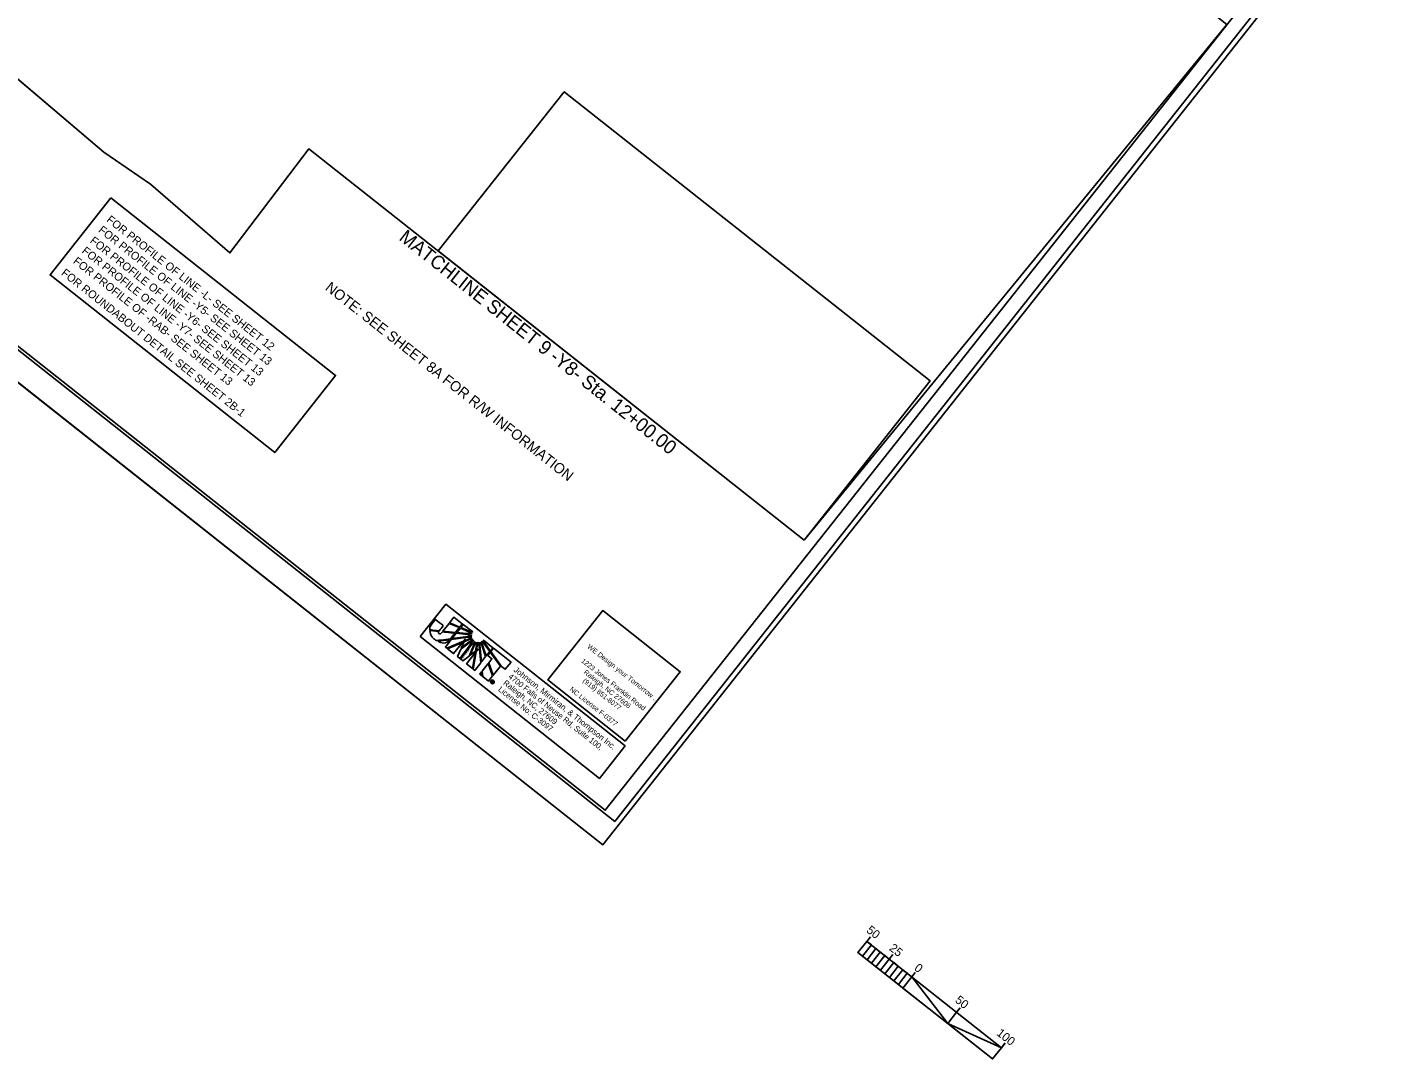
# Model space of a CAD drawing. Extents: x 557005 to 559009, y 505746 to 507841.
# Drawn here: x 557823 to 559009, y 505746 to 506649 of the extents above; entities that cross this region are included whole.
import ezdxf

# ---------------------------------------------------------------- set-up
doc = ezdxf.new("R2010")
doc.units = 0
for name, color, linetype in [('Matchline', 7, 'Continuous'), ('Matchline Text', 7, 'Continuous'), ('Prop DSN Text', 7, 'Continuous'), ('Prop Horizontal Alignment Curve and Spiral Data', 7, 'Continuous'), ('Scratch_Level_5', 7, 'Continuous'), ('Sheet Border Standard 30in CELL', 7, 'Continuous'), ('Sheet Cutting Line CELL', 7, 'Continuous'), ('Sheet Data Field CELL', 7, 'Continuous'), ('Sheet Plot Border Inside CELL', 7, 'Continuous'), ('Sheet Plot Border Outside CELL', 7, 'Continuous'), ('Sheet Title CELL', 7, 'Continuous')]:
    doc.layers.add(name, color=color, linetype=linetype)

msp = doc.modelspace()

# ---------------------------------------------------------------- linework, layer by layer
at = {"layer": 'Matchline'}
for p, q in [((557889.7, 506539.4), (557425.5, 506933.6)), ((558069.2, 506542.3), (558000.1, 506451.2)), ((558069.1, 506542.3), (558502.2, 506199.9)), ((558285.6, 506371.1), (558289.5, 506368)), ((558191.7, 506127), (558186.3, 506120.2)), ((558200.7, 506123.3), (558191.7, 506127)), ((558196, 506132.5), (558192.1, 506127.6)), ((558192.1, 506127.6), (558201.1, 506123.8)), ((558203.3, 506126.7), (558196, 506132.5)), ((558197.3, 506119), (558200.7, 506123.3)), ((558201.1, 506123.8), (558203.3, 506126.7)), ((558204.1, 506126.1), (558202.1, 506123.5)), ((558202.1, 506123.5), (558209.6, 506120.3)), ((558212.4, 506119.6), (558204.1, 506126.1)), ((558186.3, 506120.2), (558197.3, 506119)), ((558193.7, 506112.9), (558188.5, 506106.3)), ((558189.7, 506105.3), (558204.3, 506111.4)), ((558208.5, 506115), (558193.7, 506112.9)), ((558198, 506118.3), (558194.3, 506113.7)), ((558194.3, 506113.7), (558208.5, 506115.6)), ((558207.5, 506117.3), (558198, 506118.3)), ((558201.6, 506122.9), (558198.5, 506118.9)), ((558198.5, 506118.9), (558206.7, 506118.1)), ((558209.1, 506119.7), (558201.6, 506122.9)), ((558204.3, 506111.4), (558205.8, 506113.3)), ((558209.2, 506112.8), (558204.8, 506110.9)), ((558205.8, 506113.3), (558205.1, 506111.7)), ((558205.1, 506111.7), (558208.8, 506113.3)), ((558206.7, 506118.1), (558211.7, 506118.1)), ((558211.4, 506116.5), (558207.5, 506117.3)), ((558208.5, 506115.6), (558211.4, 506116.5)), ((558211.6, 506115), (558208.5, 506115)), ((558208.8, 506113.3), (558211.6, 506115)), ((558208.8, 506106.1), (558213.1, 506112.2)), ((558211.7, 506118.1), (558209.1, 506119.7)), ((558212.1, 506113.5), (558209.2, 506112.8)), ((558209.6, 506120.3), (558212.4, 506119.6)), ((558210.1, 506111.4), (558212.1, 506113.5)), ((558213.1, 506112.2), (558210.2, 506110.6)), ((558229.9, 506105.7), (558221.8, 506112.2)), ((558221.8, 506112.2), (558223.1, 506109.6)), ((558188.5, 506106.3), (558189.7, 506105.3)), ((558203.4, 506110.4), (558190.3, 506104.8)), ((558190.3, 506104.8), (558195.7, 506100.5)), ((558195.7, 506100.5), (558203.4, 506110.4)), ((558201.9, 506104.3), (558199.1, 506097.9)), ((558201.1, 506096.3), (558208.8, 506106.1)), ((558209.4, 506105.7), (558201.6, 506095.9)), ((558210.2, 506110.6), (558201.9, 506104.3)), ((558202.4, 506105.5), (558210.1, 506111.4)), ((558204.8, 506110.9), (558202.4, 506105.5)), ((558214.6, 506101.2), (558207.1, 506091.6)), ((558209.2, 506098.4), (558213.4, 506108.1)), ((558214.3, 506111.2), (558209.4, 506105.7)), ((558214.1, 506108.1), (558210.2, 506099.2)), ((558210.2, 506099.2), (558214.9, 506102.7)), ((558212.3, 506087.5), (558214.6, 506101.2)), ((558215.4, 506102.2), (558212.9, 506087)), ((558213.4, 506108.1), (558214.3, 506111.2)), ((558215.7, 506110.6), (558214.1, 506108.1)), ((558214.9, 506102.7), (558215.7, 506107.6)), ((558217.1, 506104.4), (558215.4, 506102.2)), ((558216.3, 506107.4), (558215.6, 506103.2)), ((558215.6, 506103.2), (558217.1, 506104.4)), ((558215.7, 506107.6), (558215.7, 506110.6)), ((558217.3, 506110.5), (558216.3, 506107.4)), ((558218.1, 506107.4), (558217.3, 506110.5)), ((558219.4, 506092.5), (558218.1, 506107.4)), ((558218.9, 506110.7), (558218.7, 506107.5)), ((558218.7, 506107.5), (558220, 506093.3)), ((558220.6, 506107), (558218.9, 506110.7)), ((558220.4, 506111.3), (558221.5, 506106.3)), ((558222.4, 506109.2), (558220.4, 506111.3)), ((558223.7, 506098), (558220.6, 506107)), ((558221.5, 506106.3), (558224.2, 506098.7)), ((558227.4, 506102.5), (558222.4, 506109.2)), ((558223.1, 506109.6), (558227.8, 506103.1)), ((558224.2, 506098.7), (558227.4, 506102.5)), ((558227.8, 506101.9), (558225.5, 506098.9)), ((558227.8, 506103.1), (558229.9, 506105.7)), ((558227.8, 506101.9), (558227.8, 506101.9)), ((558236.7, 506089.7), (558227.8, 506101.9)), ((558230.5, 506105.3), (558228.2, 506102.5)), ((558228.2, 506102.5), (558228.2, 506102.4)), ((558228.2, 506102.4), (558237.7, 506089.4)), ((558245.9, 506093.1), (558230.5, 506105.3)), ((558199.1, 506097.9), (558201.1, 506096.3)), ((558201.6, 506095.9), (558203.7, 506094.3)), ((558203.7, 506094.3), (558209.2, 506098.4)), ((558207.1, 506091.6), (558212.3, 506087.5)), ((558214.2, 506085.9), (558219.4, 506092.5)), ((558220, 506093.3), (558223.7, 506098)), ((558226, 506091.8), (558220.8, 506085.3)), ((558225.5, 506098.9), (558229.2, 506096)), ((558229.8, 506081), (558226, 506091.8)), ((558229.2, 506096), (558226.4, 506092.4)), ((558226.4, 506092.4), (558230.3, 506081.6)), ((558230.3, 506081.6), (558236.7, 506089.7)), ((558237.7, 506089.4), (558240.9, 506086.8)), ((558240.9, 506086.8), (558245.9, 506093.1)), ((558212.9, 506087), (558214.2, 506085.9)), ((558220.2, 506084.5), (558218.6, 506082.5)), ((558218.6, 506082.5), (558220.5, 506081)), ((558220.5, 506081), (558220.2, 506084.5)), ((558220.8, 506085.3), (558221.2, 506080.4)), ((558221.2, 506080.4), (558226.2, 506076.5)), ((558226.2, 506076.5), (558229.8, 506081)), ((558228.7, 506075.6), (558229.6, 506076.8)), ((558229.3, 506075.9), (558228.9, 506075.4)), ((558229.5, 506075.7), (558229.3, 506075.9)), ((558229.7, 506076.3), (558229.5, 506076.1)), ((558229.5, 506076.1), (558229.7, 506075.9)), ((558229.7, 506075.9), (558229.5, 506075.7)), ((558229.5, 506075.7), (558229.7, 506075.9)), ((558229.6, 506076.8), (558230, 506076.4)), ((558229.9, 506076.2), (558229.7, 506076.3)), ((558229.7, 506075.9), (558229.7, 506075.9)), ((558230, 506076.4), (558229.9, 506076.2)), ((558229.9, 506076.2), (558230, 506076.4)), ((558229.9, 506076.2), (558229.9, 506076.2)), ((558230, 506076.4), (558230.1, 506076.3)), ((558230.6, 506077.1), (558230.4, 506076.8)), ((558230.4, 506076.8), (558230.6, 506077.1)), ((558228.8, 506074.8), (558228.6, 506074.6)), ((558228.6, 506074.6), (558228.8, 506074.8)), ((558228.6, 506074.6), (558228.6, 506074.6)), ((558228.9, 506075.4), (558228.7, 506075.6)), ((558228.8, 506074.8), (558228.8, 506074.8)), ((558229.5, 506075.7), (558229.5, 506075.7))]:
    msp.add_line(p, q, dxfattribs=at)
msp.add_lwpolyline([(558166.4, 506115.5), (558323.3, 505991.4), (558345.7, 506019.7), (558188.8, 506143.8)], close=True, dxfattribs=at)
for points in [[(558186.3, 506120.2), (558197.3, 506119), (558200.7, 506123.3), (558191.7, 506127), (558186.3, 506120.2)], [(558192.1, 506127.6), (558201.1, 506123.8), (558203.3, 506126.7), (558196, 506132.5), (558192.1, 506127.6)], [(558209.6, 506120.3), (558212.4, 506119.6), (558204.1, 506126.1), (558202.1, 506123.5), (558209.6, 506120.3)], [(558211.6, 506115), (558208.5, 506115), (558193.7, 506112.9), (558188.5, 506106.3), (558189.7, 506105.3), (558204.3, 506111.4), (558205.8, 506113.3), (558205.1, 506111.7), (558208.8, 506113.3), (558211.6, 506115)], [(558198, 506118.3), (558194.3, 506113.7), (558208.5, 506115.6), (558211.4, 506116.5), (558207.5, 506117.3), (558198, 506118.3)], [(558201.6, 506122.9), (558198.5, 506118.9), (558206.7, 506118.1), (558211.7, 506118.1), (558209.1, 506119.7), (558201.6, 506122.9)], [(558210.2, 506110.6), (558201.9, 506104.3), (558199.1, 506097.9), (558201.1, 506096.3), (558208.8, 506106.1), (558213.1, 506112.2), (558210.2, 506110.6)], [(558212.1, 506113.5), (558209.2, 506112.8), (558204.8, 506110.9), (558202.4, 506105.5), (558210.1, 506111.4), (558212.1, 506113.5)], [(558223.1, 506109.6), (558227.8, 506103.1), (558229.9, 506105.7), (558221.8, 506112.2), (558223.1, 506109.6)], [(558190.3, 506104.8), (558195.7, 506100.5), (558203.4, 506110.4), (558190.3, 506104.8)], [(558214.3, 506111.2), (558209.4, 506105.7), (558201.6, 506095.9), (558203.7, 506094.3), (558209.2, 506098.4), (558213.4, 506108.1), (558214.3, 506111.2)], [(558207.1, 506091.6), (558212.3, 506087.5), (558214.6, 506101.2), (558207.1, 506091.6)], [(558215.7, 506110.6), (558214.1, 506108.1), (558210.2, 506099.2), (558214.9, 506102.7), (558215.7, 506107.6), (558215.7, 506110.6)], [(558217.3, 506110.5), (558216.3, 506107.4), (558215.6, 506103.2), (558217.1, 506104.4), (558215.4, 506102.2), (558212.9, 506087), (558214.2, 506085.9), (558219.4, 506092.5), (558218.1, 506107.4), (558217.3, 506110.5)], [(558218.9, 506110.7), (558218.7, 506107.5), (558220, 506093.3), (558223.7, 506098), (558220.6, 506107), (558218.9, 506110.7)], [(558220.4, 506111.3), (558221.5, 506106.3), (558224.2, 506098.7), (558227.4, 506102.5), (558222.4, 506109.2), (558220.4, 506111.3)], [(558227.8, 506101.9), (558227.8, 506101.9), (558225.5, 506098.9), (558229.2, 506096), (558226.4, 506092.4), (558230.3, 506081.6), (558236.7, 506089.7), (558227.8, 506101.9)], [(558245.9, 506093.1), (558230.5, 506105.3), (558228.2, 506102.5), (558228.2, 506102.4), (558237.7, 506089.4), (558240.9, 506086.8), (558245.9, 506093.1)], [(558226, 506091.8), (558220.8, 506085.3), (558221.2, 506080.4), (558226.2, 506076.5), (558229.8, 506081), (558226, 506091.8), (558226, 506091.8)], [(558218.6, 506082.5), (558218.6, 506082.5), (558220.5, 506081), (558220.2, 506084.5), (558218.6, 506082.5)], [(558229.8, 506075.2), (558229.8, 506075.1), (558229.8, 506075), (558229.7, 506075), (558229.7, 506074.9), (558229.4, 506075)]]:
    msp.add_lwpolyline(points, dxfattribs=at)
for points, degree in [([(558186.7, 506125), (558186.7, 506125), (558179.9, 506130.4), (558179.9, 506130.4), (558179.9, 506130.4), (558176.5, 506126.1), (558176.5, 506126.1), (558176.5, 506126.1), (558176.2, 506125.7), (558176.2, 506125.7), (558175.1, 506124.3), (558174.7, 506122.9), (558174.8, 506121.4), (558174.8, 506121.4), (558183.1, 506120.4), (558183.1, 506120.5), (558183.1, 506120.5), (558186.7, 506125), (558186.7, 506125)], 3), ([(558182.9, 506118), (558182.5, 506118.4), (558182.3, 506118.9), (558182.8, 506119.9), (558182.8, 506119.9), (558174.9, 506120.8), (558174.9, 506120.8), (558175.2, 506117.8), (558177, 506114.7), (558179.2, 506113), (558179.7, 506112.5), (558180.2, 506112.2), (558180.9, 506111.9), (558180.9, 506111.9), (558192.9, 506113.5), (558192.9, 506113.5), (558192.9, 506113.5), (558196.8, 506118.4), (558196.8, 506118.4), (558196.8, 506118.4), (558185.8, 506119.6), (558185.8, 506119.6), (558184.3, 506117.7), (558183.5, 506117.6), (558182.9, 506118)], 3), ([(558182.9, 506118), (558182.5, 506118.4), (558182.3, 506118.9), (558182.8, 506119.9), (558182.8, 506119.9), (558174.9, 506120.8), (558174.9, 506120.8), (558175.2, 506117.8), (558177, 506114.7), (558179.2, 506113), (558179.7, 506112.5), (558180.2, 506112.2), (558180.9, 506111.9), (558180.9, 506111.9), (558192.9, 506113.5), (558192.9, 506113.5), (558192.9, 506113.5), (558196.8, 506118.4), (558196.8, 506118.4), (558196.8, 506118.4), (558185.8, 506119.6), (558185.8, 506119.6), (558184.3, 506117.7), (558183.5, 506117.6), (558182.9, 506118)], 3), ([(558192.3, 506112.7), (558192.3, 506112.7), (558181.9, 506111.3), (558181.9, 506111.3), (558185.3, 506109.8), (558189.5, 506109.5), (558192.3, 506112.7)], 3), ([(558228.6, 506074.6), (558228.3, 506074.9), (558228.1, 506075.2), (558228, 506075.7), (558228, 506076.1), (558228.1, 506076.5), (558228.3, 506076.8), (558228.6, 506077.2), (558229, 506077.4), (558229.4, 506077.4), (558229.8, 506077.4), (558230.2, 506077.3), (558230.6, 506077.1)], 3), ([(558230.4, 506076.8), (558230.1, 506077), (558229.8, 506077.1), (558229.5, 506077.1), (558229.1, 506077.1), (558228.8, 506076.9), (558228.6, 506076.6), (558228.4, 506076.3), (558228.3, 506076), (558228.3, 506075.7), (558228.4, 506075.3), (558228.5, 506075.1), (558228.8, 506074.8)], 3), ([(558228.8, 506074.8), (558229.1, 506074.6), (558229.4, 506074.5), (558229.7, 506074.6), (558230.1, 506074.6), (558230.4, 506074.8), (558230.6, 506075), (558230.8, 506075.3), (558230.9, 506075.6), (558230.9, 506076), (558230.8, 506076.3), (558230.7, 506076.6), (558230.4, 506076.8)], 3), ([(558229.7, 506075.9), (558229.8, 506075.8), (558230, 506075.8), (558230, 506075.9), (558230.1, 506075.9), (558230.1, 506076), (558229.9, 506076.2)], 3), ([(558230.1, 506076.3), (558230.4, 506076.1), (558230.4, 506075.9), (558230.3, 506075.7), (558230.2, 506075.6), (558230.1, 506075.5), (558229.9, 506075.5)], 3), ([(558230.6, 506077.1), (558230.9, 506076.8), (558231.1, 506076.4), (558231.2, 506076), (558231.2, 506075.6), (558231.1, 506075.2), (558230.8, 506074.8)], 3), ([(558230.8, 506074.8), (558230.6, 506074.5), (558230.2, 506074.3), (558229.8, 506074.2), (558229.4, 506074.2), (558229, 506074.3), (558228.6, 506074.6)], 3), ([(558229.4, 506075), (558229.5, 506075.1), (558229.5, 506075.2), (558229.6, 506075.3), (558229.6, 506075.4), (558229.7, 506075.5), (558229.7, 506075.5)], 3), ([(558229.7, 506075.5), (558229.7, 506075.6), (558229.6, 506075.6), (558229.5, 506075.7)], 2), ([(558229.9, 506075.5), (558230, 506075.4), (558230, 506075.3), (558229.8, 506075.2)], 2)]:
    msp.add_open_spline(points, degree=degree, dxfattribs=at)
at = {"layer": 'Prop DSN Text'}
msp.add_lwpolyline([(558345.9, 506024), (558278.2, 506077.5), (558326.1, 506138.2), (558393.9, 506084.7)], close=True, dxfattribs=at)
at = {"layer": 'Prop Horizontal Alignment Curve and Spiral Data'}
msp.add_lwpolyline([(557895.9, 506499.3), (557842.7, 506432), (558039.2, 506276.6), (558092.5, 506344), (557895.9, 506499.3)], dxfattribs=at)
at = {"layer": 'Scratch_Level_5'}
for points in [[(558502.2, 506199.9), (558069.1, 506542.3), (558000.1, 506451.2), (557930.7, 506511.3), (557889.7, 506539.4), (557425.5, 506933.6), (557393.3, 506960), (557371.4, 506969.7), (557385.3, 506999.1), (557443.2, 507138.3), (557378.9, 507175.5), (557803.8, 507716.9), (558807.2, 506891.6), (558715.1, 506775.1), (558872, 506651)], [(558502.2, 506199.9), (558182.2, 506452.9), (558292.5, 506592.3), (558612.5, 506339.3)]]:
    msp.add_lwpolyline(points, close=True, dxfattribs=at)
at = {"layer": 'Sheet Border Standard 30in CELL'}
msp.add_lwpolyline([(558979.7, 506787.1), (557803.1, 507717.5), (557151.8, 506893.8), (558328.4, 505963.5)], close=True, dxfattribs=at)
at = {"layer": 'Sheet Cutting Line CELL'}
msp.add_line((557005.3, 506977.8), (558326.3, 505933.3), dxfattribs=at)
at = {"layer": 'Sheet Data Field CELL'}
for p, q in [((558557.2, 505848.7), (558560.3, 505852.6)), ((558576.8, 505833.2), (558579.9, 505837.1)), ((558635.6, 505786.7), (558638.7, 505790.6)), ((558674.9, 505755.7), (558678, 505759.6))]:
    msp.add_line(p, q, dxfattribs=at)
at = {"layer": 'Sheet Plot Border Inside CELL'}
msp.add_lwpolyline([(558991.1, 506781.4), (557683.8, 507815), (557029.4, 506987.4), (558336.7, 505953.7)], close=True, dxfattribs=at)
at = {"layer": 'Sheet Plot Border Outside CELL'}
msp.add_lwpolyline([(559008.5, 506796.2), (557687.6, 507840.7), (557005.3, 506977.8), (558326.3, 505933.3)], close=True, dxfattribs=at)
at = {"layer": 'Sheet Title CELL'}
for p, q in [((558557.2, 505848.7), (558560.3, 505852.6)), ((558557.2, 505848.7), (558549.4, 505838.9)), ((558549.4, 505838.9), (558667.1, 505745.9)), ((558674.8, 505755.7), (558557.2, 505848.7)), ((558576.8, 505833.2), (558579.9, 505837.1)), ((558584.6, 505827), (558576.9, 505817.2)), ((558596.4, 505817.7), (558599.5, 505821.6)), ((558635.6, 505786.7), (558627.9, 505776.9)), ((558635.6, 505786.7), (558638.7, 505790.6)), ((558667.1, 505745.9), (558674.8, 505755.7)), ((558674.8, 505755.7), (558677.9, 505759.6))]:
    msp.add_line(p, q, dxfattribs=at)
for points in [[(558557.2, 505848.7), (558561.1, 505845.6), (558553.3, 505835.8), (558549.4, 505838.9)], [(558565, 505842.5), (558568.9, 505839.4), (558561.2, 505829.6), (558557.3, 505832.7)], [(558572.9, 505836.3), (558576.8, 505833.2), (558569, 505823.4), (558565.1, 505826.5)], [(558580.7, 505830.1), (558584.6, 505827), (558576.9, 505817.2), (558573, 505820.3)], [(558588.6, 505823.9), (558592.5, 505820.8), (558584.7, 505811), (558580.8, 505814.1)], [(558596.4, 505817.7), (558627.9, 505776.9), (558588.6, 505807.9)], [(558674.8, 505755.7), (558627.9, 505776.9), (558667.1, 505745.9)]]:
    msp.add_lwpolyline(points, close=True, dxfattribs=at)

# ---------------------------------------------------------------- texts
at = {"layer": 'Matchline'}
for s, height, rotation, p in [('www.jmt.com', 1.241, 231.6667, (558209.1, 506104.3)), ('Johnson, Mirmiran, & Thompson Inc.', 5.111, 321.6667, (558247.7, 506085.4)), ('Raleigh, NC, 27609', 4.965, 321.6667, (558238.6, 506074)), ('4700 Falls of Neuse Rd, Suite 100, ', 4.965, 321.6667, (558243, 506079.6)), ('License No: C-3097', 4.965, 321.6667, (558234.2, 506068.4))]:
    msp.add_text(s, height=height, rotation=rotation, dxfattribs=at).set_placement(p)
at = {"layer": 'Matchline Text'}
msp.add_text('MATCHLINE SHEET 9 -Y8- Sta. 12+00.00', height=12, rotation=321.4798, dxfattribs=at).set_placement((558147.1, 506463.1))
at = {"layer": 'Prop DSN Text'}
for s, p in [('WE Design your Tomorrow ...', (558312.2, 506105.9)), ('1223 Jones Franklin Road', (558306.9, 506093.5)), ('(919) 851-8077', (558308.2, 506076)), ('Raleigh, NC 27606', (558309.1, 506083.5)), ('NC License F-0377', (558296.8, 506068.5))]:
    msp.add_text(s, height=4.32, rotation=321.6831, dxfattribs=at).set_placement(p)
at = {"layer": 'Prop Horizontal Alignment Curve and Spiral Data'}
for s, height, rotation, p in [('FOR PROFILE OF LINE -L- SEE SHEET 12', 7, 321.6834, (557891.5, 506479.1)), ('FOR PROFILE OF LINE -Y5- SEE SHEET 13', 7, 321.6834, (557884.4, 506470.1)), ('FOR PROFILE OF LINE -Y7- SEE SHEET 13', 7, 321.6834, (557869.9, 506451.8)), ('FOR PROFILE OF LINE -Y6- SEE SHEET 13', 7, 321.6834, (557877, 506460.7)), ('FOR PROFILE OF -RAB- SEE SHEET 13', 7, 321.6667, (557862.3, 506442.8)), ('FOR ROUNDABOUT DETAIL SEE SHEET 2B-1', 7, 321.6667, (557851.9, 506432.5)), ('NOTE: SEE SHEET 8A FOR R/W INFORMATION', 9.1, 321.6834, (558082.7, 506419.4))]:
    msp.add_text(s, height=height, rotation=rotation, dxfattribs=at).set_placement(p)
at = {"layer": 'Sheet Title CELL'}
for s, p in [('50', (558556.2, 505857.3)), ('25', (558576.1, 505841.6)), ('0', (558598, 505824.2)), ('50', (558633.7, 505796.1)), ('100', (558670, 505767.3))]:
    msp.add_text(s, height=7.5, rotation=321.6714, dxfattribs=at).set_placement(p)

doc.saveas('drawing.dxf')
